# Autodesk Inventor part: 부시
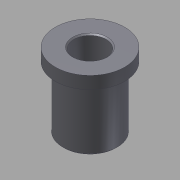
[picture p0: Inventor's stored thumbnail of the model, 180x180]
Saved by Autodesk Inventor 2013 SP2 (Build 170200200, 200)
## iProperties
Company: 한국ATC센터
Created: 2015-11
Part Number: 부시
Document SubType Name: Modeling
Designer: mdu
Density: 7.86 g/cm^3
Material: 강철, 연강
Mass: 67.5146 g
Surface Area: 43.3569 cm^2
Volume: 8.58964 cm^3
Author: mdu
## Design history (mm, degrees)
sketch "스케치1"
  geometry: C1 r 11 at (0, 0) reference; C2 r 14 at (0, 0) reference; C3 r 11 at (0, 0) reference; 1 further point
  node "참조1"
  node "참조2"
extrude "돌출1" new body sketch "스케치1" distance "d0" = 5; taper "d1" = 0 deg
extrude "돌출2" join sketch "스케치1" distance "d2" = 25; taper "d3" = 0 deg
hole "구멍1" diameter "d6" = 13; stored, may be unused: countersink angle "d10" = 90 deg, drill point angle "d12" = 118 deg; dims "d4" = 10, "d5" = 10, "d7" = 6, "d8" = 4, "d9" = 2, "d11" = 8
chamfer "모따기1" distance "d13" = 0.5; stored, may be unused: second distance "d14" = 2, angle "d15" = 45 deg
chamfer "모따기2" distance "d16" = 0.5; stored, may be unused: second distance "d17" = 2, angle "d18" = 45 deg
node "솔리드1"
